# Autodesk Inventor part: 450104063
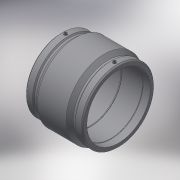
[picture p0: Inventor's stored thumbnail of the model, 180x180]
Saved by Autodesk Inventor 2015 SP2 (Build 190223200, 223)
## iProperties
Created: 2017-06
Part Number: 450104063
Material: Generic
Description: PLASSON COUPLER 63 PN25
Document SubType Name: Modeling
Designer: KIM
Mass: 8622.19 g
Surface Area: 6772.47 cm^2
Volume: 8622.19 cm^3
Density: 1 g/cm^3
Appearance: Default
Author: KIM
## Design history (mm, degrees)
derived "450104.ipt"
feature "Solid1::450104.ipt"
tag "TaggingFeature1"
body "Solid1"
other parameters: "d0" = 118, "d1" = 63, "d2" = 82, "d3" = 57, "d4" = 29.5, "d5" = 73.8, "d6" = 50.4, "d7" = 63, "d8" = 168 deg, "d10" = 22.8, "d11" = 7.6, "d13" = 118, "d14" = 17.6296, "d15" = 57, "d16" = 57, "d17" = 62.37, "d18" = 63, "d19" = 3.52592, "d20" = 168 deg, "d22" = 77.08, "d23" = 82, "d24" = 74.7676, "d25" = 135 deg, "d26" = 53.1, "d27" = 135 deg, "d29" = 58, "d30" = 15, "d31" = 41.3, "d34" = 5 deg, "d35" = 15, "d39" = 5 deg, "d41" = 4, "d42" = 14, "d43" = 0, "d45" = 4, "d46" = 14, "d47" = 0, "d48" = 3, "d49" = 0, "d50" = 3, "d51" = 0, "d52" = 16.53, "d53" = 4.1325, "d_" = 63, "L_" = 118, "L_1" = 57, "D_" = 82, "A_" = 58, "d_2" = 12
